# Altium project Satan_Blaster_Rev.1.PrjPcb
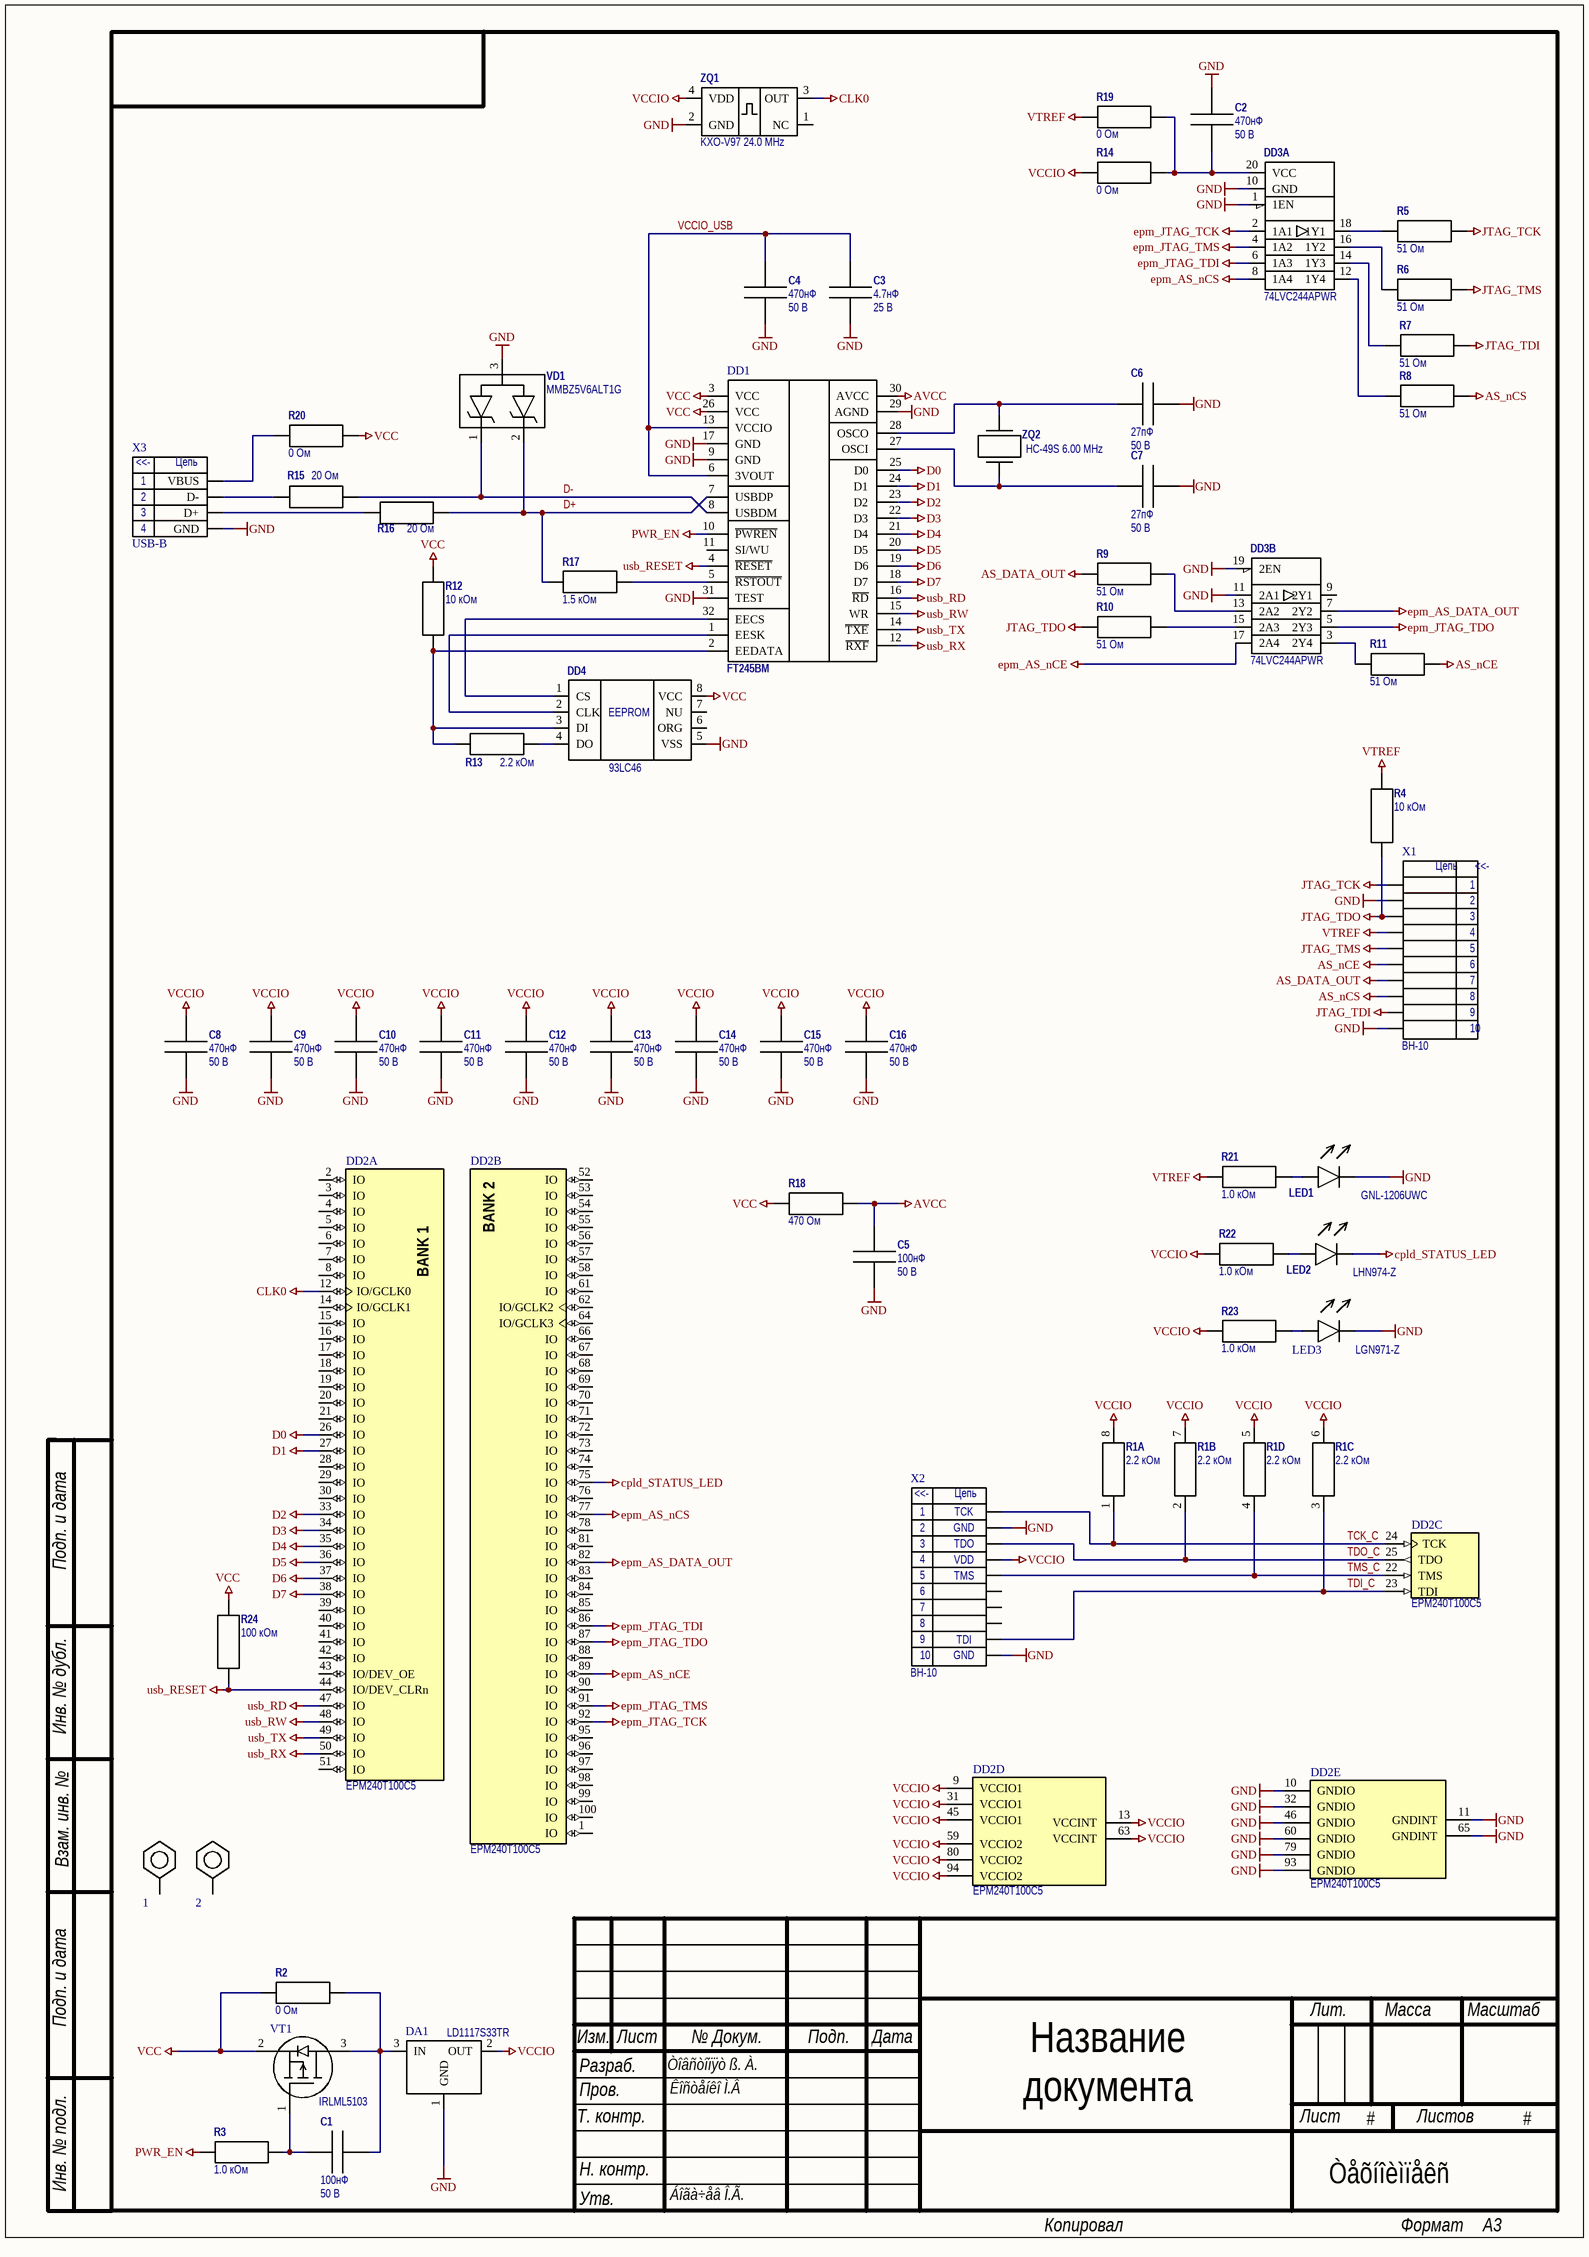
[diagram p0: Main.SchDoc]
Firma: Òåõíîèìïåêñ; Proveril: Êîñòåíêî Ì.Â; Razrabotal: Òîâñòîïÿò ß. À.; Utverdil: Áîãà÷åâ Î.Ã.
1 sheet, 57 parts. Net scope: global (net labels, ports and power ports of the same name join across sheets).
Board file: SATAN_BLASTER_Rev.1.PcbDoc

## Sheet Main.SchDoc
size custom portrait

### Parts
1  M3  [M3]  (value not drawn)
2  M3  [M3]  (value not drawn)
C1  value 100нФ  VOLTAGE: 50 В  [C0805]  (hidden comment: 100нФ  10%  50В 0805 X7R)
C2  value 470нФ  VOLTAGE: 50 В  [C0805]  (hidden comment: 470нФ 10% 50 В)
C3  value 4.7нФ  VOLTAGE: 25 В  [C0805]  (hidden comment: 4.7нФ  5%  25В 0805 NPO)
C4  value 470нФ  VOLTAGE: 50 В  [C0805]  (hidden comment: 470нФ 10% 50 В)
C5  value 100нФ  VOLTAGE: 50 В  [C0805]  (hidden comment: 100нФ  10%  50В 0805 X7R)
C6  value 27пФ  VOLTAGE: 50 В  [C0805]  (hidden comment: 27пФ  5%  50В 0805 NPO)
C7  value 27пФ  VOLTAGE: 50 В  [C0805]  (hidden comment: 27пФ  5%  50В 0805 NPO)
C8  value 470нФ  VOLTAGE: 50 В  [C0805]  (hidden comment: 470нФ 10% 50 В)
C9  value 470нФ  VOLTAGE: 50 В  [C0805]  (hidden comment: 470нФ 10% 50 В)
C10  value 470нФ  VOLTAGE: 50 В  [C0805]  (hidden comment: 470нФ 10% 50 В)
C11  value 470нФ  VOLTAGE: 50 В  [C0805]  (hidden comment: 470нФ 10% 50 В)
C12  value 470нФ  VOLTAGE: 50 В  [C0805]  (hidden comment: 470нФ 10% 50 В)
C13  value 470нФ  VOLTAGE: 50 В  [C0805]  (hidden comment: 470нФ 10% 50 В)
C14  value 470нФ  VOLTAGE: 50 В  [C0805]  (hidden comment: 470нФ 10% 50 В)
C15  value 470нФ  VOLTAGE: 50 В  [C0805]  (hidden comment: 470нФ 10% 50 В)
C16  value 470нФ  VOLTAGE: 50 В  [C0805]  (hidden comment: 470нФ 10% 50 В)
DA1  LD1117S33TR  [SOT-223]
DD1  FT245BM  [LQFP-32-P0.8]
DD2  EPM240T100C5  [TQFP-100]  (parts A,B,C,D,E of 5)
DD3  74LVC244APWR  [TSSOP-20]  (parts A,B of 2)
DD4  93LC46  [SO-8]
LED1  GNL-1206UWC  [LED1206W]
LED2  LHN974-Z  [LED1206R]
LED3  LGN971-Z  [LED1206G]
R1  value 2.2 кОм  [4D03]  (hidden comment: 2.2 кОм 4D03)  (parts A,B,C,D of 4)
R2  value 0 Ом  [R0805]  (hidden comment: 0 Ом 0805 5%)
R3  value 1.0 кОм  [R0805]  (hidden comment: 1.0 кОм 0805 5%)
R4  value 10 кОм  [R0805]  (hidden comment: 10 кОм 0805 5%)
R5  value 51 Ом  [R0805]  (hidden comment: 51 Ом 0805 5%)
R6  value 51 Ом  [R0805]  (hidden comment: 51 Ом 0805 5%)
R7  value 51 Ом  [R0805]  (hidden comment: 51 Ом 0805 5%)
R8  value 51 Ом  [R0805]  (hidden comment: 51 Ом 0805 5%)
R9  value 51 Ом  [R0805]  (hidden comment: 51 Ом 0805 5%)
R10  value 51 Ом  [R0805]  (hidden comment: 51 Ом 0805 5%)
R11  value 51 Ом  [R0805]  (hidden comment: 51 Ом 0805 5%)
R12  value 10 кОм  [R0805]  (hidden comment: 10 кОм 0805 5%)
R13  value 2.2 кОм  [R0805]  (hidden comment: 2.2 кОм 0805 5%)
R14  value 0 Ом  [R0805]  (hidden comment: 0 Ом 0805 5%)
R15  value 20 Ом  [R0805]  (hidden comment: 20 Ом 0805 5%)
R16  value 20 Ом  [R0805]  (hidden comment: 20 Ом 0805 5%)
R17  value 1.5 кОм  [R0805]  (hidden comment: 1.5 кОм 0805 5%)
R18  value 470 Ом  [R0805]  (hidden comment: 470 Ом 0805 5%)
R19  value 0 Ом  [R0805]  (hidden comment: 0 Ом 0805 5%)
R20  value 0 Ом  [R1206]  (hidden comment: 0 Ом 1206 5%)
R21  value 1.0 кОм  [R0805]  (hidden comment: 1.0 кОм 0805 5%)
R22  value 1.0 кОм  [R0805]  (hidden comment: 1.0 кОм 0805 5%)
R23  value 1.0 кОм  [R0805]  (hidden comment: 1.0 кОм 0805 5%)
R24  value 100 кОм  [R0805]  (hidden comment: 100 кОм 0805 5%)
VD1  MMBZ5V6ALT1G  [SOT-23]
VT1  IRLML5103  [SOT-23]
X1  BH-10  [BH-10]
X2  BH-10  [BH-10]
X3  USB-B  [USB-B]
ZQ1  KXO-V97 24.0 MHz  [KXO-97]
ZQ2  HC-49S 6.00 MHz  [HC-49S]

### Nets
AS_DATA_OUT: R9.1 X1.7
AS_nCE: R11.2 X1.6
AS_nCS: R8.2 X1.8
AVCC: C5.1 DD1.30(AVCC) R18.2
CLK0: DD2.12(IO/GCLK0) ZQ1.3(OUT)
cpld_STATUS_LED: DD2.75(IO) LED2.2
D0: DD1.25(D0) DD2.26(IO)
D1: DD1.24(D1) DD2.27(IO)
D2: DD1.23(D2) DD2.33(IO)
D3: DD1.22(D3) DD2.34(IO)
D4: DD1.21(D4) DD2.35(IO)
D5: DD1.20(D5) DD2.36(IO)
D6: DD1.19(D6) DD2.37(IO)
D7: DD1.18(D7) DD2.38(IO)
epm_AS_DATA_OUT: DD2.82(IO) DD3.7(2Y2)
epm_AS_nCE: DD2.89(IO) DD3.17(2A4)
epm_AS_nCS: DD2.77(IO) DD3.8(1A4)
epm_JTAG_TCK: DD2.92(IO) DD3.2(1A1)
epm_JTAG_TDI: DD2.86(IO) DD3.6(1A3)
epm_JTAG_TDO: DD2.87(IO) DD3.5(2Y3)
epm_JTAG_TMS: DD2.91(IO) DD3.4(1A2)
GND: C2.1 C3.1 C4.1 C5.2 C6.2 C7.2 C8.2 C9.2 C10.2 C11.2 C12.2 C13.2 C14.2 C15.2 C16.2 DA1.1(GND) DD1.9(GND) DD1.17(GND) DD1.29(AGND) DD1.31(TEST) DD2.10(GNDIO) DD2.11(GNDINT) DD2.32(GNDIO) DD2.46(GNDIO) DD2.60(GNDIO) DD2.65(GNDINT) DD2.79(GNDIO) DD2.93(GNDIO) DD3.1(1EN) DD3.10(GND) DD3.11(2A1) DD3.19(2EN) DD4.5(VSS) LED1.2 LED3.2 VD1.3 X1.2 X1.10 X2.2 X2.10 X3.4(GND) ZQ1.2(GND)
JTAG_TCK: R5.2 X1.1
JTAG_TDI: R7.2 X1.9
JTAG_TDO: R4.1 R10.1 X1.3
JTAG_TMS: R6.2 X1.5
PWR_EN: DD1.10(~{PWREN}) R3.1
usb_RD: DD1.16(~{RD}) DD2.47(IO)
usb_RESET: DD1.4(~{RESET}) DD2.44(IO/DEV_CLRn) R24.1
usb_RW: DD1.15(WR) DD2.48(IO)
usb_RX: DD1.12(~{RXF}) DD2.50(IO)
usb_TX: DD1.14(~{TXE}) DD2.49(IO)
VCC: DD1.3(VCC) DD1.26(VCC) DD4.8(VCC) R2.1 R12.2 R18.1 R20.2 R24.2 VT1.2(S)
VCCIO: C8.1 C9.1 C10.1 C11.1 C12.1 C13.1 C14.1 C15.1 C16.1 DA1.2(OUT) DD2.9(VCCIO1) DD2.13(VCCINT) DD2.31(VCCIO1) DD2.45(VCCIO1) DD2.59(VCCIO2) DD2.63(VCCINT) DD2.80(VCCIO2) DD2.94(VCCIO2) R1.5 R1.6 R1.7 R1.8 R14.1 R22.1 R23.1 X2.4 ZQ1.4(VDD)
VTREF: R4.2 R19.1 R21.1 X1.4
D+: DD1.7(USBDP) R16.2 R17.1 VD1.2
D-: DD1.8(USBDM) R15.2 VD1.1
TCK_C: DD2.24(TCK) R1.1 X2.1
TDI_C: DD2.23(TDI) R1.3 X2.9
TDO_C: DD2.25(TDO) R1.2 X2.3
TMS_C: DD2.22(TMS) R1.4 X2.5
VCCIO_USB: C3.2 C4.2 DD1.6(3VOUT) DD1.13(VCCIO)
NetC1_1: C1.1 R3.2 VT1.1(G)
NetC1_2: C1.2 DA1.3(IN) R2.2 VT1.3(D)
NetC2_2: C2.2 DD3.20(VCC) R14.2 R19.2
NetC6_1: C6.1 DD1.28(OSCO) ZQ2.2
NetC7_1: C7.1 DD1.27(OSCI) ZQ2.1
NetDD1_1: DD1.1(EESK) DD4.2(CLK)
NetDD1_2: DD1.2(EEDATA) DD4.3(DI) R12.1 R13.2
NetDD1_5: DD1.5(~{RSTOUT}) R17.2
NetDD1_32: DD1.32(EECS) DD4.1(CS)
NetDD3_3: DD3.3(2Y4) R11.1
NetDD3_12: DD3.12(1Y4) R8.1
NetDD3_13: DD3.13(2A2) R9.2
NetDD3_14: DD3.14(1Y3) R7.1
NetDD3_15: DD3.15(2A3) R10.2
NetDD3_16: DD3.16(1Y2) R6.1
NetDD3_18: DD3.18(1Y1) R5.1
NetDD4_4: DD4.4(DO) R13.1
NetLED1_1: LED1.1 R21.2
NetLED2_1: LED2.1 R22.2
NetLED3_1: LED3.1 R23.2
NetR15_1: R15.1 X3.2(D-)
NetR16_1: R16.1 X3.3(D+)
NetR20_1: R20.1 X3.1(VBUS)

Not connected (* = marked no-connect by the designer): 1 0; 2 0; DD1 11(SI/WU); DD2 1(IO) 2(IO) 3(IO) 4(IO) 5(IO) 6(IO) 7(IO) 8(IO) 14(IO/GCLK1) 15(IO) 16(IO) 17(IO) 18(IO) 19(IO) 20(IO) 21(IO) 28(IO) 29(IO) 30(IO) 39(IO) 40(IO) 41(IO) 42(IO) 43(IO/DEV_OE) 51(IO) 52(IO) 53(IO) 54(IO) 55(IO) 56(IO) 57(IO) 58(IO) 61(IO) 62(IO/GCLK2) 64(IO/GCLK3) 66(IO) 67(IO) 68(IO) 69(IO) 70(IO) 71(IO) 72(IO) 73(IO) 74(IO) 76(IO) 78(IO) 81(IO) 83(IO) 84(IO) 85(IO) 88(IO) 90(IO) 95(IO) 96(IO) 97(IO) 98(IO) 99(IO) 100(IO); DD3 9(2Y1); DD4 6(ORG) 7(NU); X2 6 7 8; ZQ1 1(NC)

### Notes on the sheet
- (near X2) TCK
- (near X2) GND
- Подп. и дата
- (near X2) TDO
- (near X2) TMS
- (near X2) VDD
- (near X2) TDI
- Инв. № дубл.
- Взам. инв. №
- Изм.
- Лист
- № Докум.
- Подп.
- Дата
- Лит.
- Масса
- Масштаб
- Т. контр.
- Разраб.
- Пров.
- Название
  документа
- #
- Листов
- Инв. № подл.
- Н. контр.
- Утв.
- Копировал
- Формат
- А3

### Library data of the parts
C1 C5 = 100нФ  50В: конденсатор керамический; Designator: capacitor
C2 C4 C8-C16 = 470нФ 50 В: конденсатор керамический SMD; Library Reference: capacitor; articul: 389
C3 = 4.7нФ  25В: конденсатор керамический; Library Reference: capacitor; articul: 388
C6 C7 = 27пФ  50В: конденсатор керамический; Library Reference: capacitor; articul: 392
DA1 = LD1117S33TR: Positive 3.3V SOT-223; articul: 81
DD1 = FT245BM: FT245R USB FIFO
DD2 = EPM240T100C5: MAX II 3.3/2.5V CPLD, 80 IOs, 240 Logic Elements, 100-Pin Plastic TQFP, Commercial Temperature, Speed Grade 5; articul: 402
DD3 = 74LVC244APWR: 8-ми разрядный буфер
DD4 = 93LC46: Serial EEPROM
LED1 = GNL-1206UWC: Белый светодиод; articul: 496
LED2 = LHN974-Z: Красный светодиод Uvd - 1.84 В
LED3 = LGN971-Z: Зеленый светодиод Uvd - 2.2 В; articul: 19
R1 = 2.2 кОм 4D03: Массив резисторов; Library Reference: 4X; articul: 138
R2 R14 R19 = 0 Ом 0805 5%: резистор постоянный; articul: 88
R3 R21-R23 = 1.0 кОм 0805 5%: резистор постоянный; articul: 94
R4 R12 = 10 кОм 0805 5%: резистор постоянный; articul: 89
R5-R11 = 51 Ом 0805 5%: резистор постоянный; articul: 466
R13 = 2.2 кОм 0805 5%: резистор постоянный; articul: 551
R15 R16 = 20 Ом 0805 5%: резистор постоянный; articul: 594
R17 = 1.5 кОм 0805 5%: резистор постоянный; articul: 71
R18 = 470 Ом 0805 5%: резистор постоянный; articul: 0
R20 = 0 Ом 1206 5%: резистор постоянный; articul: 20
R24 = 100 кОм 0805 5%: резистор постоянный; articul: 84
VD1 = MMBZ5V6ALT1G: Сдвоенный сапрессор
VT1 = IRLML5103: HEXFET Power MOSFET; Id: -0.76A; Vds: -30V
X1 X2 = BH-10: вилка IDC на плату прямая; articul: 37
X3 = USB-B: USB Fimale connector type B
ZQ1 = KXO-V97 24.0 MHz: Кварцевый генератор
ZQ2 = HC-49S 6.00 MHz: Кварцевый резонатор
